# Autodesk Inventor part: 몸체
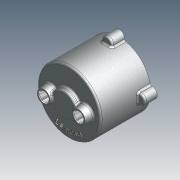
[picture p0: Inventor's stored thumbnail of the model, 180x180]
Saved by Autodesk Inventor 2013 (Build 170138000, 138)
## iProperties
Company: 한국ATC센터
Created: 2012-05
Part Number: 몸체
Document SubType Name: 모델링
Designer: KYOUNG IL JANG
Mass: 471.045 g
Surface Area: 679.307 cm^2
Volume: 173.817 cm^3
Density: 2.71 g/cm^3
Material: 알루미늄-6061
변환 표준: STEP AP214IS
파일 이름: C:\Users\SeoGD\Desktop\?쒗뿕\紐몄껜.stp
전처리기: Build: 253, Release: 2010 SP1 - Date: Wed 07/29/2009
전송 단위: 밀리미터
불확실성: 0.01
Author: KYOUNG IL JANG
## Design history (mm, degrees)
sketch "스케치2"
  geometry: C1 r 50 at (0, 0); 1 further point
  constraints: 1 centre point, 1 coincident
  dimensions: "d9" = 100 diameter of C1
extrude "돌출2" new body sketch "스케치2" distance "d10" = 80; taper "d11" = 0 deg
feature "쉘1" dims "d12" = 5
sketch "스케치3" dims "d13" = 55
  geometry: C1 r 7.5 at (27.5, 0); C2 r 12.5 at (27.5, 0); 2 further points
  constraints: 2 centre point, 2 coincident, 2 horizontal alignment, 2 other
  dimensions: "d14" = 15 diameter of C1; "d15" = 25 diameter of C2
extrude "돌출3" join sketch "스케치3" distance "d16" = 12; taper "d17" = -10 deg
hole "구멍2" diameter "d20" = 15; stored, may be unused: countersink angle "d24" = 90 deg, drill point angle "d26" = 118 deg; dims "d18" = 10, "d19" = 10, "d21" = 6, "d22" = 4, "d23" = 2, "d25" = 15
chamfer "모따기1" distance "d27" = 1; stored, may be unused: second distance "d28" = 2, angle "d29" = 45 deg
sketch "스케치4"
  geometry: L1 (0, 0)-(0, 88); L2 (0, 70)-(13.16, 70); L3 (-45, 75)-(45, 75) reference; L4 (-50, 80)-(50, 80) reference; L5 (13.16, 70)-(14.5, 75); L6 (20, 80)-(20, 88); L7 (20, 88)-(0, 88); L8 (20, 80)-(14.5, 75)
  constraints: 12 end point, 3 point on line, 2 perpendicular, 1 vertical
  dimensions: "d34" = 40 diameter of L6 L1; "d35" = 105 deg angle of L5 L3; "d36" = 5 distance between parallel lines of L2 L3; "d37" = 8 distance between parallel lines of L7 L4; "d51" = 29 diameter of L5.end L1
revolve "회전1" sketch "스케치4" stored, may be unused: angle "d38" = 90 deg
hole "구멍3" diameter "d41" = 15; stored, may be unused: countersink angle "d45" = 90 deg, drill point angle "d47" = 0 deg; dims "d39" = 10, "d40" = 10, "d42" = 6, "d43" = 22, "d44" = 13, "d46" = 15
chamfer "모따기2" distance "d48" = 1; stored, may be unused: second distance "d49" = 2, angle "d50" = 45 deg
fillet "모깎기1" dims "d52" = 3
fillet "모깎기2" dims "d53" = 3, "d72" = 0.2
sketch "스케치5"
  geometry: A1 r 50 centre (0, 0) between (50, 0) and (-8.074, 49.344) reference; A2 r 8.5 centre (0, 52) between (8.074, 49.344) and (-8.074, 49.344); 1 further point
  constraints: 5 point on circle, 1 centre point, 1 horizontal alignment
  dimensions: "d54" = 90 deg dimension on point (0, 0) A2.centre A1.start; "d55" = 52 distance of A2.centre point (0, 0); "d56" = 17 diameter of A2
extrude "돌출4" join sketch "스케치5" distance "d57" = 20; taper "d58" = 0 deg
fillet "모깎기3" dims "d59" = 3
hole "구멍4" diameter "d62" = 4.134; stored, may be unused: countersink angle "d66" = 90 deg, drill point angle "d68" = 118 deg; dims "d60" = 10, "d61" = 10, "d63" = 12, "d64" = 22, "d65" = 13, "d67" = 15
sketch "스케치6"
  geometry: C1 r 47 at (0, 0) reference; C2 r 42.5 at (0, 0); 1 further point
  constraints: 1 centre point, 1 coincident, 1 other
  dimensions: "d73" = 85 diameter of C2
feature "엠보싱1" sketch "스케치6" dims "d74" = 1, "d75" = 0
node "솔리드1"
node "솔리드 본체"
node "곡면 본체"
pattern_circular "원형 패턴1" dims "d31" = 360 deg
pattern_circular "원형 패턴2" dims "d70" = 360 deg
node "솔리드2"
